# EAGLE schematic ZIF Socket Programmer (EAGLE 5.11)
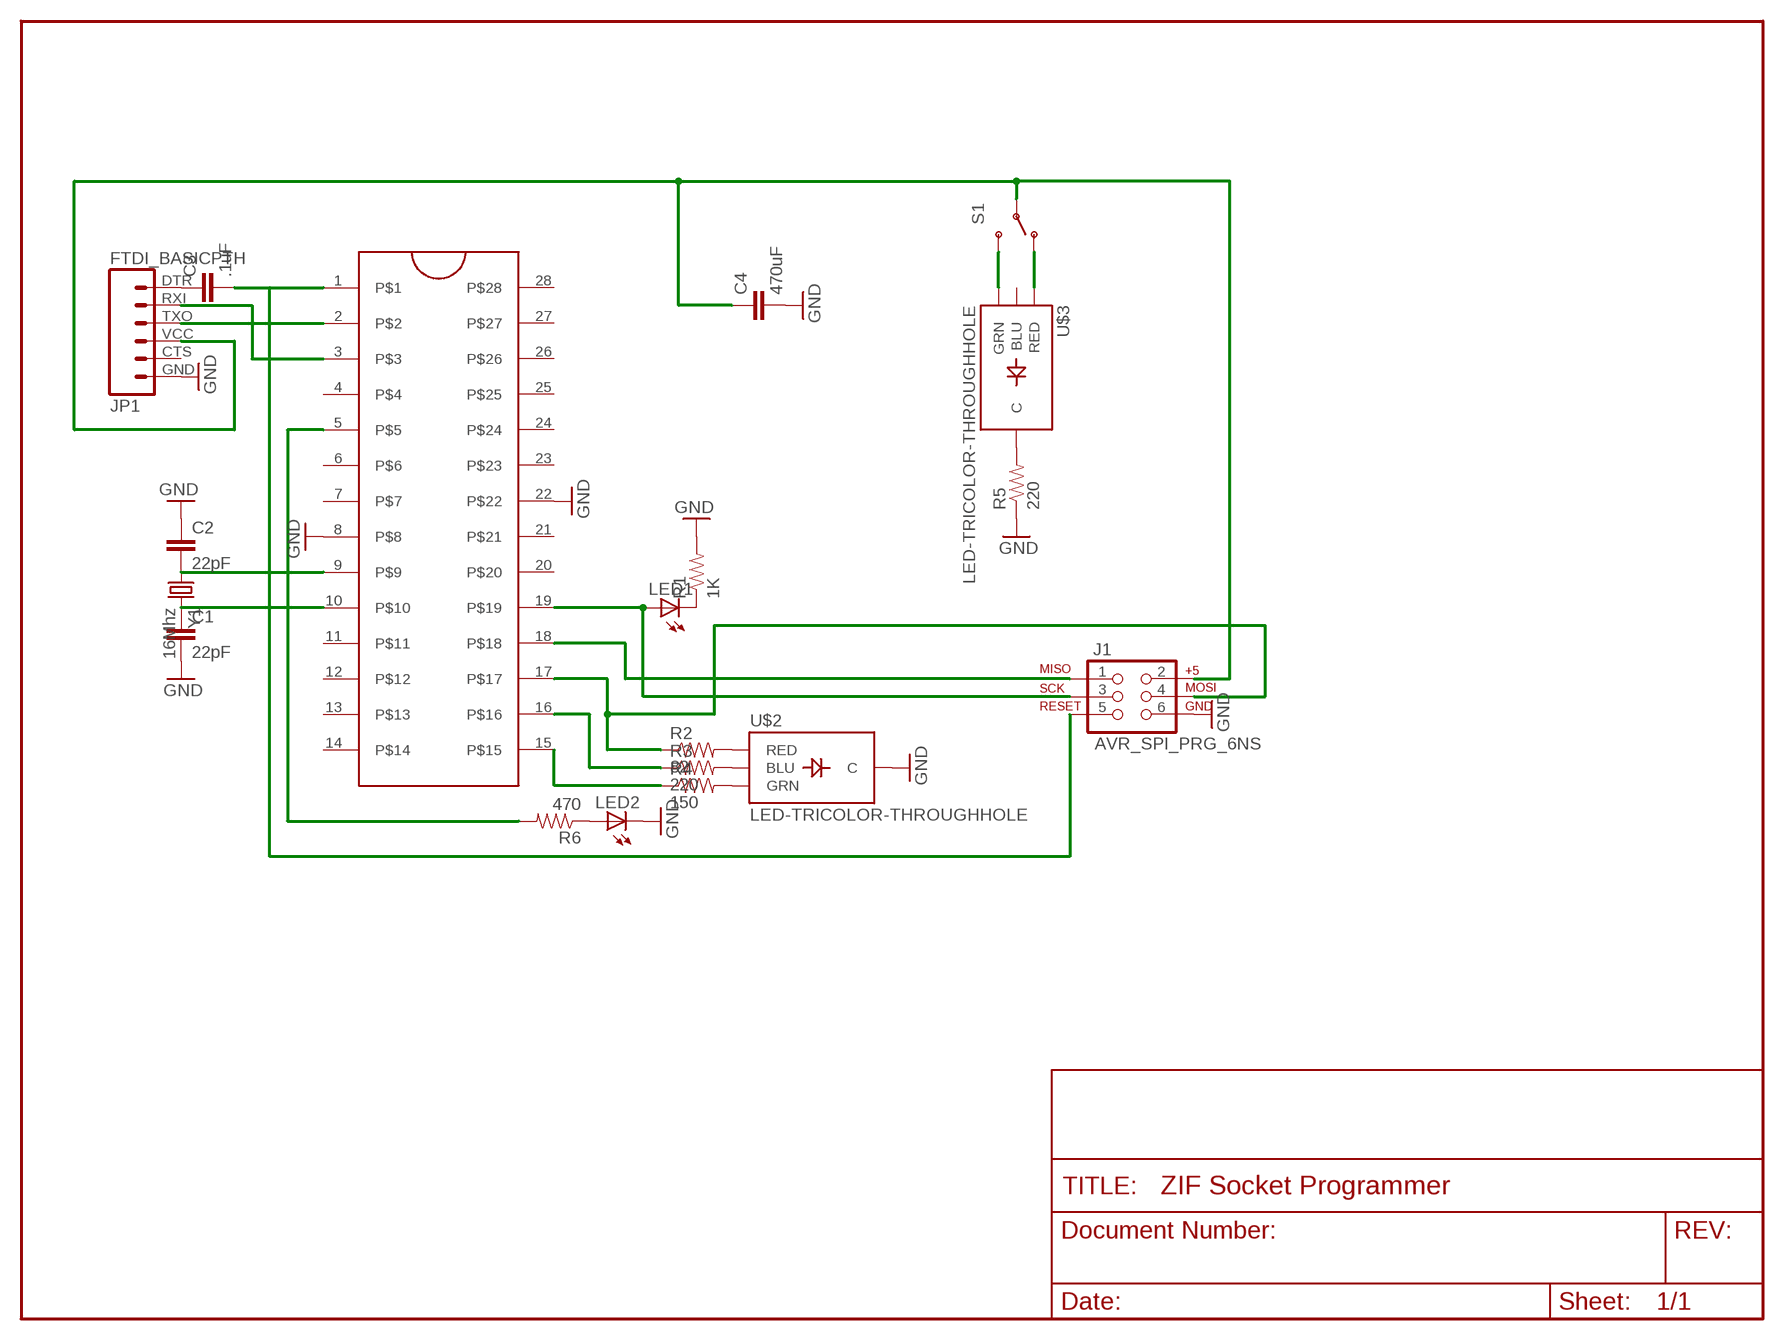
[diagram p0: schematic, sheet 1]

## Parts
C1  22pF  CAPKIT  [CAP-PTH-SMALL-KIT]
C2  22pF  CAPKIT  [CAP-PTH-SMALL-KIT]
C3  .1uF  CAPKIT  [CAP-PTH-SMALL-KIT]
C4  470uF  CAPPTH3  [CAP-PTH-LARGE]
J1  AVR_SPI_PRG_6NS  [2X3-NS]
JP1  FTDI_BASICPTH  [FTDI_BASIC]
LED1  LED3MM  [LED3MM]
LED2  LED3MM  [LED3MM]
R1  1K  RESISTORPTH-1/4W  [AXIAL-0.4]
R2  82  RESISTORPTH-1/4W  [AXIAL-0.4]
R3  220  RESISTORPTH-1/4W  [AXIAL-0.4]
R4  150  RESISTORPTH-1/4W  [AXIAL-0.4]
R5  220  RESISTORPTH-1/4W  [AXIAL-0.4]
R6  470  RESISTORPTH-1/4W  [AXIAL-0.4]
S1  SWITCH-SPSTSMD2  [SWITCH-SPDT-SMD]
U$1  ZIFSOCKET-28-3ZIFFSOCKET-28-3  [DIL28-3-ZIF_SOCKET]
U$2  LED-TRICOLOR-THROUGHHOLE  [LED-TRICOLOR-THROUGHHOLE]
U$3  LED-TRICOLOR-THROUGHHOLE  [LED-TRICOLOR-THROUGHHOLE]
Y1  16Mhz  CRYSTALHC49US  [HC49US]

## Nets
GND: C1.2 C2.1 C4.2 J1.6 JP1.GND LED2.K(C) R1.P$2 R5.P$1 U$1.8 U$1.22 U$2.GND(C)
N$1: J1.1 U$1.18
N$2: J1.3 LED1.A U$1.19
N$3: C3.2 J1.5 U$1.1
N$4: C3.1 JP1.DTR
N$5: LED1.K(C) R1.P$1
N$6: R2.P$2 U$2.RED
N$7: R3.P$2 U$2.BLU
N$8: R4.P$2 U$2.GRN
N$9: R5.P$2 U$3.GND(C)
N$10: LED2.A R6.P$1
N$11: C1.1 U$1.10 Y1.2
N$12: C2.2 U$1.9 Y1.1
N$13: JP1.RXI U$1.3
N$14: JP1.TXO U$1.2
N$15: C4.1 J1.2 JP1.VCC S1.2(P)
N$16: J1.4 R2.P$1 U$1.17
N$17: R3.P$1 U$1.16
N$18: R4.P$1 U$1.15
N$19: S1.3(S) U$3.GRN
N$20: S1.1(O) U$3.RED
N$23: R6.P$2 U$1.5
Unconnected: JP1.CTS U$1.4 U$1.6 U$1.7 U$1.11 U$1.12 U$1.13 U$1.14 U$1.20 U$1.21 U$1.23 U$1.24 U$1.25 U$1.26 U$1.27 U$1.28 U$3.BLU

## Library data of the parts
C1-C4 = SparkFun:CAP: Capacitor
J1 = SparkFun:AVR_SPI_PRG_6: AVR ISP 6 Pin This is the reduced ISP connector for AVR programming. Common on Arduino. This footprint will take up less PCB space and can be used with a 10-pin to 6-pin adapter such as SKU: BOB-08508
JP1 = SparkFun:FTDI_BASIC: FTDI Basic: 3.3V and 5V
LED1 LED2 = SparkFun:LED: LEDs
R1-R6 = SparkFun:RESISTOR: Resistor
S1 = SparkFun:SWITCH-SPST: SPST Switch Simple slide switch. Spark Fun Electronics SKU : COM-00102
U$1 = SparkFun:ZIFSOCKET-28-3
U$2 U$3 = SparkFun:LED-TRICOLOR-THROUGHHOLE
Y1 = SparkFun:CRYSTAL: Crystals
